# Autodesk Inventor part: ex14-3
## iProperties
Author: J. DESIGNER
Revision Number: A
Created: 2001-10
Part Number: ex14-3
Description: SUPPORT, FOOT
Document SubType Name: Modeling
Designer: J. DESIGNER
Control State: 0
Master: False
Checked Out: False
PropertySet Name: Design Tracking Control
Shininess: 64.0
Angle Display Precision: 2
Document Length Units: 11272
Document Angle Units: 11286
Document Time Units: 11279
Document Mass Units: 11290
Document Length Units Precision: 3
Document Angle Units Precision: 2
Compacted: False
PropertySet Name: _Private Model Information
Density: 0.0
Volumn: 0.0
Area: 0.0
PropertySet Name: Model Information
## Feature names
1. Extrusion1
2. Hole1
3. Extrusion3
4. Extrusion4
